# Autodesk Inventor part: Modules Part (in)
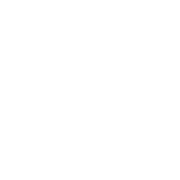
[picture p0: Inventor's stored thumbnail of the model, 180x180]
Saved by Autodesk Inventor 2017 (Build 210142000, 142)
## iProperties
Created: 2014-08
Part Number: Modules Part (in)
Material: Generic
Document SubType Name: Modeling
Designer: Wally
Manufacturer: Standard
Standards Organization: Custom
Density: 1 g/cm^3
Appearance: Default
Author: Wally
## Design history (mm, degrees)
node "Sketch1"
